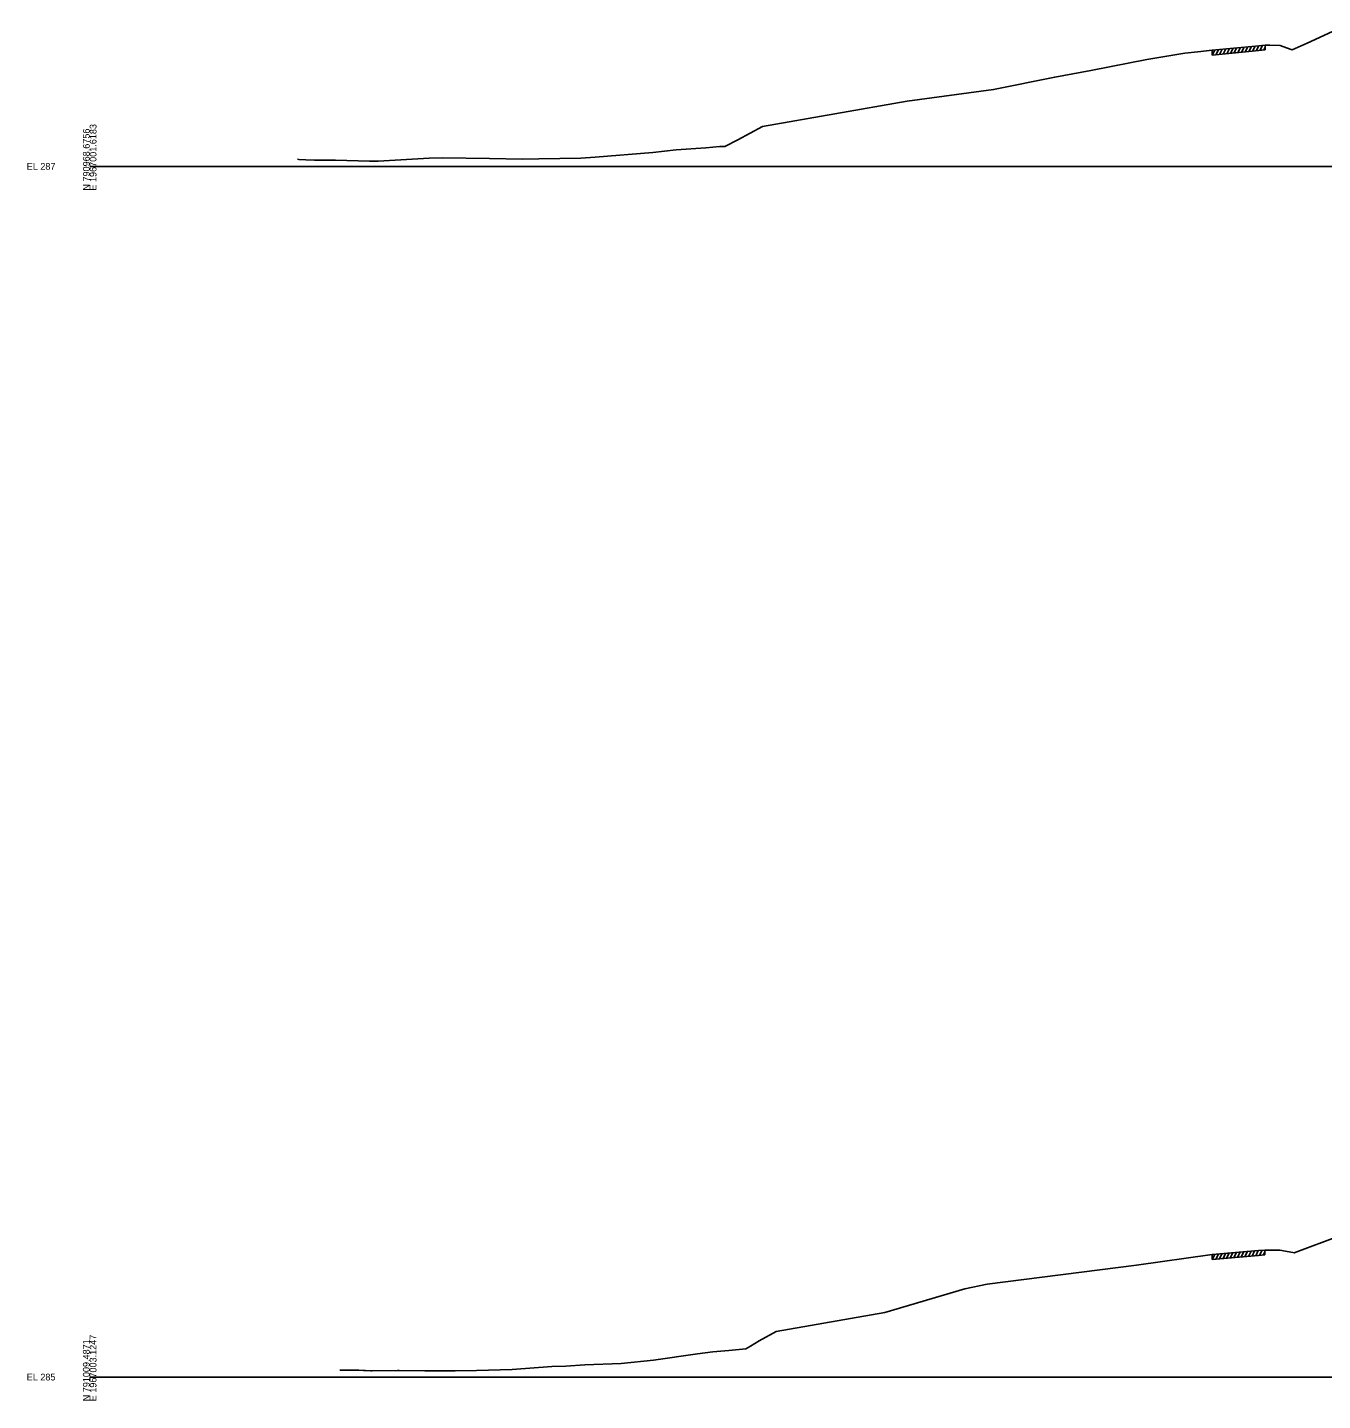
# Model space of a CAD drawing. Extents: x 1017 to 19997, y -1947 to 50737.
# Drawn here: x 17974 to 18509, y 10490 to 11057 of the extents above; entities that cross this region are included whole.
import ezdxf

# ---------------------------------------------------------------- set-up
doc = ezdxf.new("R2010")
doc.units = 0
for name, color, linetype in [('RD_GPK_XS_Cell', 7, 'Continuous'), ('RD_XS_ExGround', 7, 'Continuous'), ('RD_XS_ExPaveRet', 7, 'Continuous')]:
    doc.layers.add(name, color=color, linetype=linetype)

msp = doc.modelspace()

# ---------------------------------------------------------------- linework, layer by layer
at = {"layer": 'RD_GPK_XS_Cell'}
for p, q in [((18000, 11000), (18600, 11000)), ((18000, 10500), (18600, 10500))]:
    msp.add_line(p, q, dxfattribs=at)
at = {"layer": 'RD_XS_ExGround'}
for points in [[(18085.81, 11002.96), (18086.35, 11002.84), (18089.27, 11002.74), (18092.81, 11002.61), (18096.81, 11002.56), (18101.42, 11002.5), (18115.47, 11002.16), (18116.34, 11002.14), (18116.7, 11002.13), (18117.14, 11002.13), (18117.61, 11002.11), (18119.13, 11002.21), (18140.14, 11003.4), (18145.71, 11003.53), (18165, 11003.21), (18178.75, 11002.93), (18185.48, 11003.13), (18202.78, 11003.34), (18208.68, 11003.74), (18232.49, 11005.77), (18242.09, 11006.88), (18254.4, 11007.67), (18260.22, 11008.15), (18262.27, 11008.18), (18267.56, 11010.99), (18277.74, 11016.5), (18337.5, 11026.97), (18373.15, 11031.75), (18398.45, 11036.88), (18413.31, 11039.62), (18436.42, 11044.13), (18452.2, 11046.71), (18457.46, 11047.37), (18463.48, 11047.95), (18481.26, 11049.7), (18485.32, 11050.07), (18487.18, 11050), (18491.55, 11049.93), (18495.66, 11048.36), (18496.41, 11048.15), (18502.63, 11050.92), (18516.69, 11057.37)], [(18103.21, 10502.87), (18111.09, 10502.82), (18113, 10502.73), (18113.91, 10502.69), (18116, 10502.61), (18116.55, 10502.6), (18127.1, 10502.65), (18127.7, 10502.67), (18138.38, 10502.52), (18150.87, 10502.54), (18159.65, 10502.78), (18174.47, 10503.19), (18190.83, 10504.3), (18196.56, 10504.48), (18204.39, 10505), (18219.36, 10505.66), (18232.81, 10506.97), (18250.89, 10509.59), (18257.21, 10510.36), (18263.82, 10510.95), (18270.92, 10511.62), (18272.76, 10512.8), (18276.34, 10515.02), (18283.42, 10518.84), (18328.23, 10526.66), (18361.36, 10536.48), (18370.51, 10538.34), (18432.24, 10546.15), (18463.44, 10550.57), (18482.58, 10552.21), (18485.16, 10552.43), (18486.53, 10552.37), (18491.41, 10552.4), (18496.7, 10551.5), (18497.33, 10551.25), (18516.42, 10558.53)]]:
    msp.add_lwpolyline(points, dxfattribs=at)
at = {"layer": 'RD_XS_ExPaveRet'}
for p, q in [((18463.48, 11045.95), (18464.54, 11048.06)), ((18463.48, 11045.95), (18463.48, 11047.95)), ((18464.98, 11046.1), (18466.03, 11048.2)), ((18466.48, 11046.25), (18467.53, 11048.35)), ((18467.98, 11046.39), (18469.03, 11048.5)), ((18469.48, 11046.54), (18470.53, 11048.64)), ((18470.97, 11046.69), (18472.03, 11048.79)), ((18472.48, 11046.84), (18473.53, 11048.94)), ((18474, 11046.98), (18475.05, 11049.09)), ((18475.51, 11047.13), (18476.57, 11049.24)), ((18477.03, 11047.28), (18478.08, 11049.39)), ((18478.55, 11047.43), (18479.6, 11049.53)), ((18480.06, 11047.58), (18481.11, 11049.68)), ((18481.58, 11047.73), (18482.63, 11049.82)), ((18483.09, 11047.86), (18484.14, 11049.96)), ((18484.68, 11048.01), (18485.32, 11049.28)), ((18485.32, 11048.07), (18485.32, 11050.07)), ((18463.44, 10548.57), (18464.49, 10550.66)), ((18463.44, 10548.57), (18463.44, 10550.57)), ((18464.93, 10548.7), (18465.98, 10550.79)), ((18466.42, 10548.82), (18467.47, 10550.91)), ((18467.91, 10548.95), (18468.96, 10551.04)), ((18469.4, 10549.08), (18470.45, 10551.17)), ((18470.89, 10549.21), (18471.93, 10551.3)), ((18472.39, 10549.34), (18473.43, 10551.43)), ((18473.89, 10549.47), (18474.94, 10551.56)), ((18475.4, 10549.6), (18476.44, 10551.69)), ((18476.91, 10549.73), (18477.95, 10551.82)), ((18478.41, 10549.86), (18479.46, 10551.95)), ((18479.92, 10549.99), (18480.96, 10552.08)), ((18481.43, 10550.12), (18482.47, 10552.21)), ((18482.94, 10550.24), (18483.98, 10552.33)), ((18484.52, 10550.38), (18485.16, 10551.66)), ((18485.16, 10550.43), (18485.16, 10552.43))]:
    msp.add_line(p, q, dxfattribs=at)
for points in [[(18463.48, 11045.95), (18481.26, 11047.7), (18485.32, 11048.07)], [(18463.44, 10548.57), (18482.58, 10550.21), (18485.16, 10550.43)]]:
    msp.add_lwpolyline(points, dxfattribs=at)

# ---------------------------------------------------------------- texts
at = {"layer": 'RD_GPK_XS_Cell'}
for s, p in [('N 790968.6756', (18000, 10990)), ('E 1967001.6183', (18002.8, 10990)), ('N 791009.4871', (18000, 10490)), ('E 1967003.1247', (18002.8, 10490))]:
    msp.add_text(s, height=2.8, rotation=90, dxfattribs=at).set_placement(p)
for s, p in [('EL 287', (17974, 10998.6)), ('EL 285', (17974, 10498.6))]:
    msp.add_text(s, height=2.8, dxfattribs=at).set_placement(p)

doc.saveas('drawing.dxf')
